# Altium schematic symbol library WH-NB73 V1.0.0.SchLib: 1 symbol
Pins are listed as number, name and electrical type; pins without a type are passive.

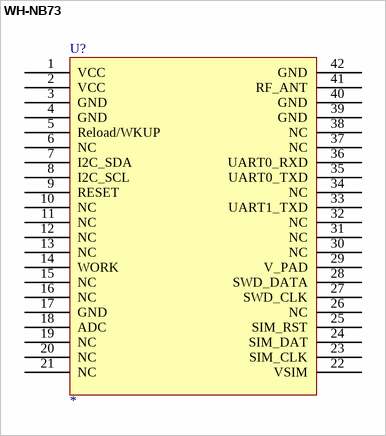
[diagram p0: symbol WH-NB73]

## WH-NB73
designator U?
pins: 1 VCC, 2 VCC, 3 GND, 4 GND, 5 Reload/WKUP, 6 NC, 7 I2C_SDA, 8 I2C_SCL, 9 RESET, 10 NC, 11 NC, 12 NC, 13 NC, 14 WORK, 15 NC, 16 NC, 17 GND, 18 ADC, 19 NC, 20 NC, 21 NC, 22 VSIM, 23 SIM_CLK, 24 SIM_DAT, 25 SIM_RST, 26 NC, 27 SWD_CLK, 28 SWD_DATA, 29 V_PAD, 30 NC, 31 NC, 32 NC, 33 UART1_TXD, 34 NC, 35 UART0_TXD, 36 UART0_RXD, 37 NC, 38 NC, 39 GND, 40 GND, 41 RF_ANT, 42 GND
2 alternate drawings of the same symbol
